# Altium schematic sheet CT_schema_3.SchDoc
size 293 x 156 mm
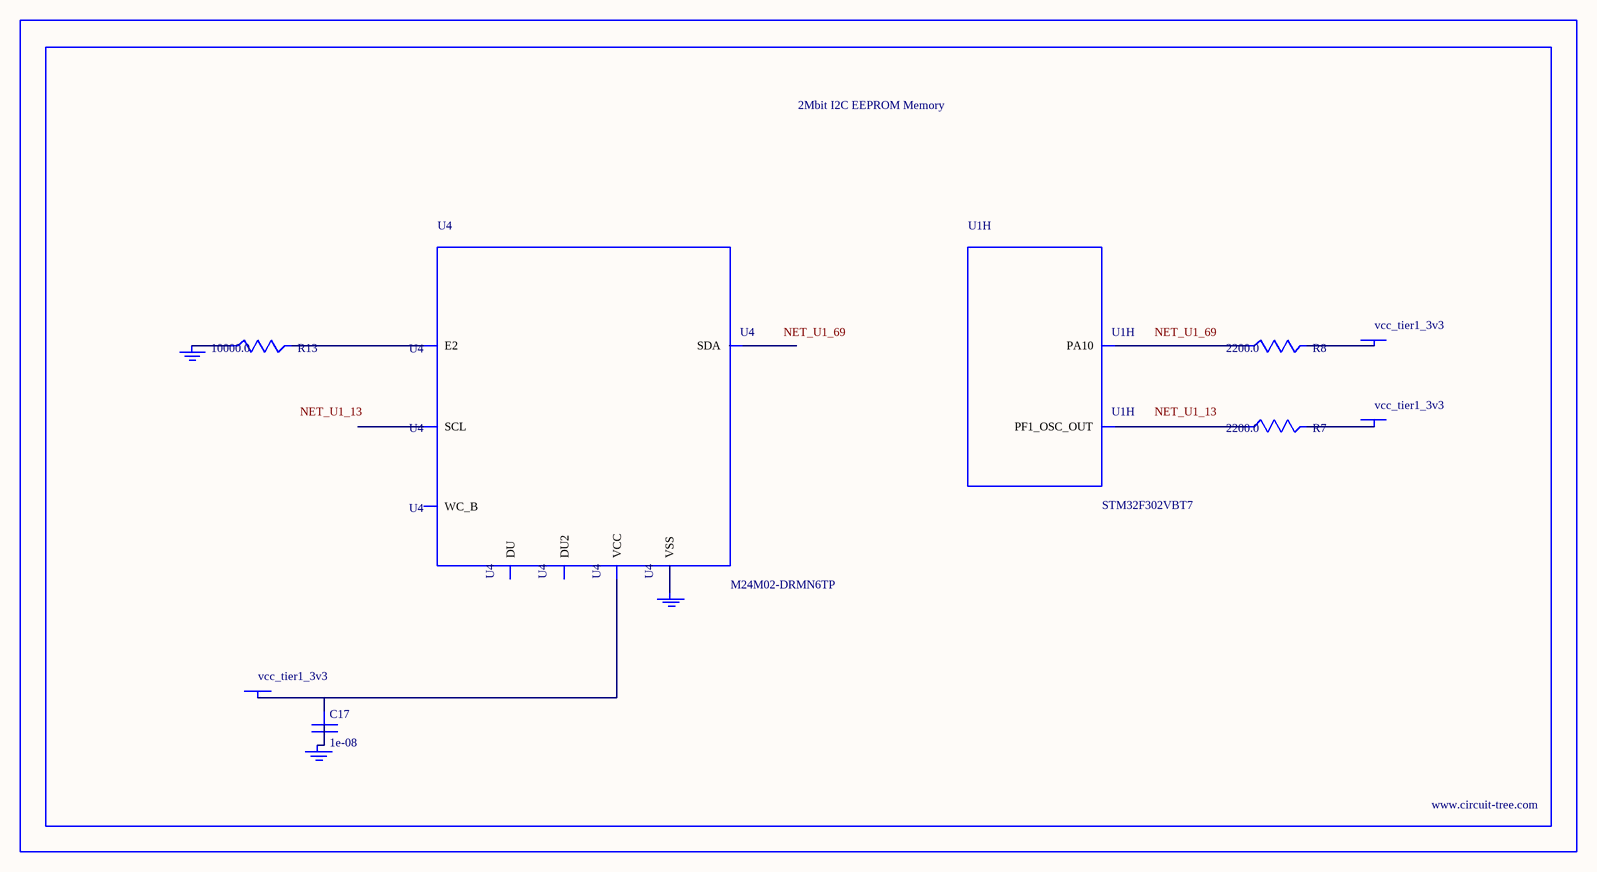
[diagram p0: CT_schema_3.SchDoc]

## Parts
BORDER2  (no value)
C17  1e-08  [C0402]
GND_INSTANCE_2_0  (no value)
GND_INSTANCE_2_1  (no value)
GND_INSTANCE_2_2  (no value)
POWER_INSTANCE_2_0  vcc_tier1_3v3
POWER_INSTANCE_2_1  vcc_tier1_3v3
POWER_INSTANCE_2_2  vcc_tier1_3v3
R7  2200.0  [R0603]
R8  2200.0  [R0603]
R13  10000.0  [R0603]
U1  STM32F302VBT7  [LQFP100]  (part H of 11)
U4  M24M02-DRMN6TP  [SOIC-8]

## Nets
NetC17_1: C17.1 POWER_INSTANCE_2_0.0(PWR) U4.8(VCC)
NetC17_2: C17.2 GND_INSTANCE_2_1.0(GND)
NetGND_INSTANCE_2_0_0: GND_INSTANCE_2_0.0(GND) R13.1
NetGND_INSTANCE_2_2_0: GND_INSTANCE_2_2.0(GND) U4.4(VSS)
NetPOWER_INSTANCE_2_1_0: POWER_INSTANCE_2_1.0(PWR) R7.2
NetPOWER_INSTANCE_2_2_0: POWER_INSTANCE_2_2.0(PWR) R8.2
NetR7_1: R7.1 U1.13(PF1_OSC_OUT)
NetR8_1: R8.1 U1.69(PA10)
NetR13_2: R13.2 U4.3(E2)

Not connected (* = marked no-connect by the designer): U4 1(DU) 2(DU2) 5(SDA) 6(SCL) 7(WC_B)

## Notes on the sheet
- Labels drawn without touching a wire or pin: NET_U1_13, NET_U1_69

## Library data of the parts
BORDER2 = BORDER_PAGE2
C17 = C0402C103K3RAC
GND_INSTANCE_2_0-GND_INSTANCE_2_2 = GND
POWER_INSTANCE_2_0-POWER_INSTANCE_2_2 = PWR
R7 R8 = RC0603JR-072K2L
R13 = RC0603JR-0710KL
